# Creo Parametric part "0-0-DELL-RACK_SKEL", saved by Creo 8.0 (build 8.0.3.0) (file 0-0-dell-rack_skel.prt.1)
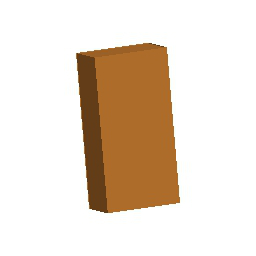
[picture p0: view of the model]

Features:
  1. datum plane "DTM1"
  2. datum plane "DTM2"
  3. datum plane "DTM3"

Other named items: REP0001

Layers: 0_ALL_AXIS, 0_ALL_CSYS, 0_ALL_CURVES, 0_ALL_PLANES, 0_ALL_POINTS, 0_ALL_SURFS

Surfaces: 6 plane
